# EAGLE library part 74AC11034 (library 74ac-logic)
Hex non-inverting DRIVER
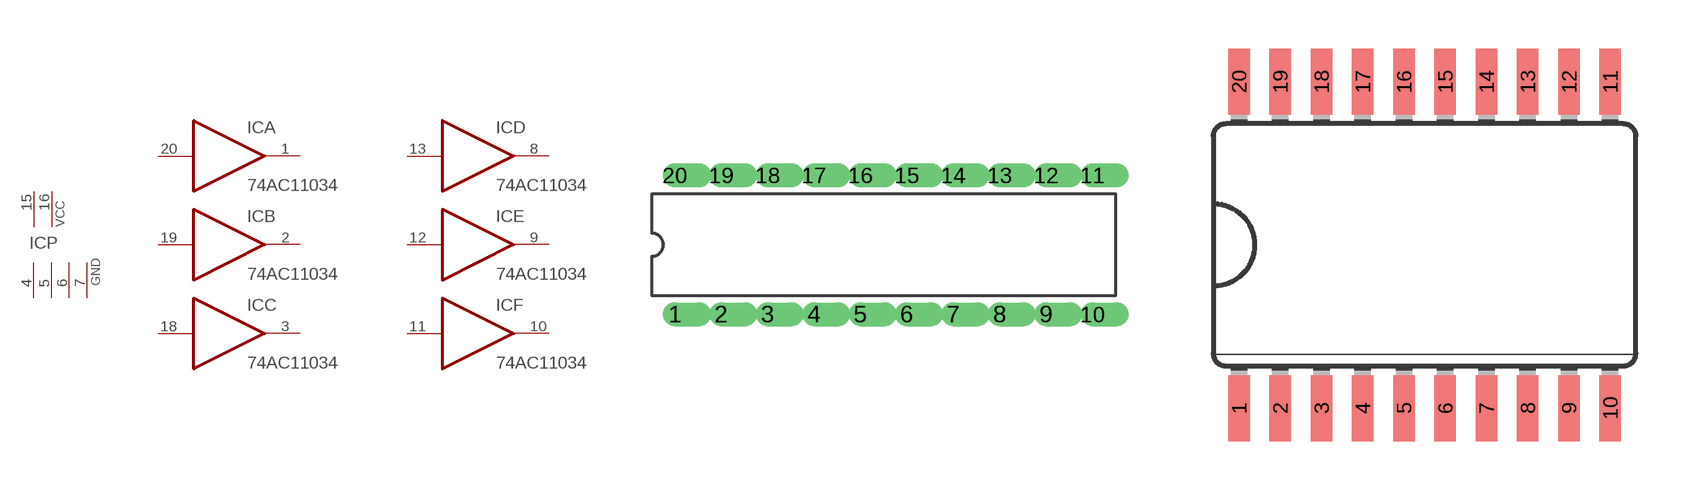
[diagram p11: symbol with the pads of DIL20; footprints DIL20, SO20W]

Designator prefix IC; gates A=7411034 B=7411034 C=7411034 D=7411034 E=7411034 F=7411034 P=2PWR4GND

## 74AC11034  [DIL20]
1  A:O  out
2  B:O  out
3  C:O  out
4  P:GND  pwr
5  P:GND  pwr
6  P:GND  pwr
7  P:GND  pwr
8  D:O  out
9  E:O  out
10  F:O  out
11  F:I  in
12  E:I  in
13  D:I  in
15  P:VCC  pwr
16  P:VCC  pwr
18  C:I  in
19  B:I  in
20  A:I  in

## 74AC11034D  [SO20W]
Pads as for DIL20

## Footprint DIL20 (pad centres in mm)
Dual In Line
drill 0.813 offset: 1 -11.43,-3.81; 2 -8.89,-3.81; 3 -6.35,-3.81; 4 -3.81,-3.81; 5 -1.27,-3.81; 6 1.27,-3.81; 7 3.81,-3.81; 8 6.35,-3.81; 9 8.89,-3.81; 10 11.43,-3.81; 11 11.43,3.81; 12 8.89,3.81; 13 6.35,3.81; 14 3.81,3.81; 15 1.27,3.81; 16 -1.27,3.81; 17 -3.81,3.81; 18 -6.35,3.81; 19 -8.89,3.81; 20 -11.43,3.81

## Footprint SO20W (pad centres in mm)
Wide Small Outline package 300 mil
smd 0.66 x 2.032: 1 -5.715,-5.029; 2 -4.445,-5.029; 3 -3.175,-5.029; 4 -1.905,-5.029; 5 -0.635,-5.029; 6 0.635,-5.029; 7 1.905,-5.029; 8 3.175,-5.029; 9 4.445,-5.029; 10 5.715,-5.029; 11 5.715,5.029; 12 4.445,5.029; 13 3.175,5.029; 14 1.905,5.029; 15 0.635,5.029; 16 -0.635,5.029; 17 -1.905,5.029; 18 -3.175,5.029; 19 -4.445,5.029; 20 -5.715,5.029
